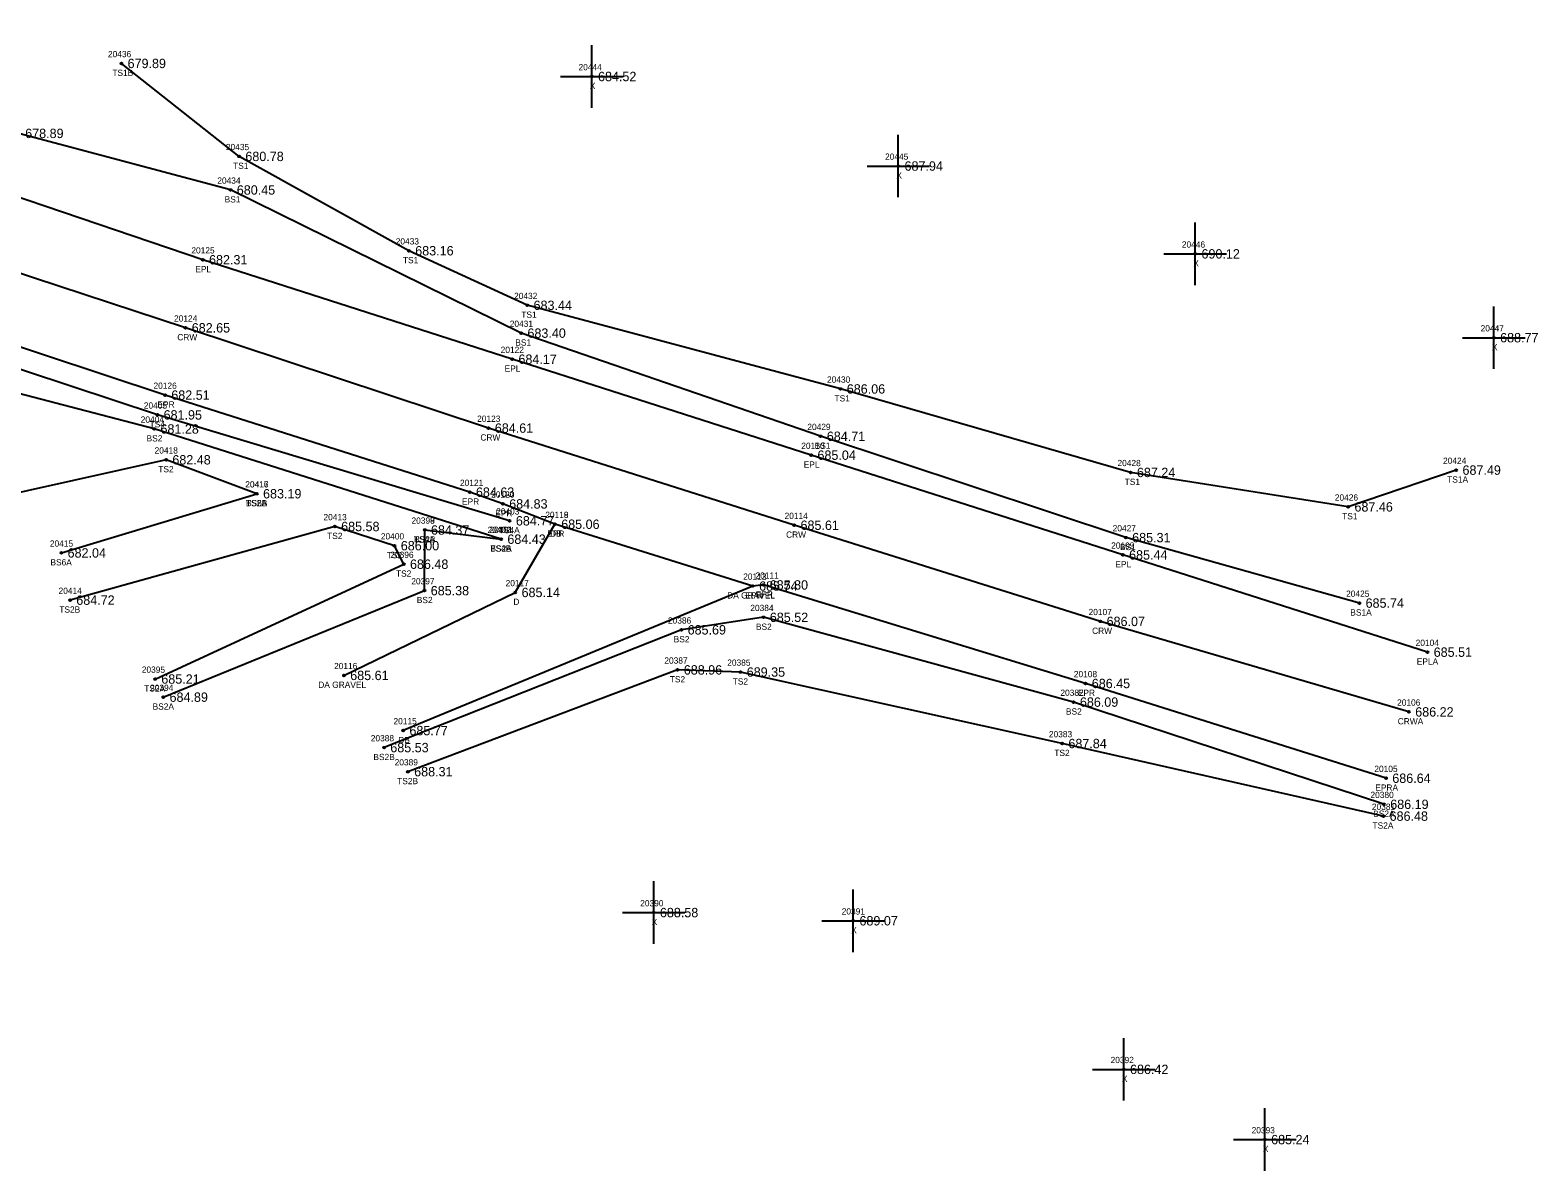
# Model space of a CAD drawing. Extents: x 1655675 to 1657082, y 1004080 to 1005193.
# Drawn here: x 1656840.9 to 1657082.1, y 1004326.1 to 1004508.6 of the extents above; entities that cross this region are included whole.
import ezdxf

# ---------------------------------------------------------------- set-up
doc = ezdxf.new("R2010")
doc.units = 0
for name, color, linetype in [('RD_DTM_BkLn1', 7, 'Continuous'), ('RD_DTM_BkLn2', 7, 'Continuous'), ('RD_DTM_BkLn_txCode', 7, 'Continuous'), ('RD_EX_Driveway', 7, 'Continuous'), ('RD_EX_Driveway_txCode', 7, 'Continuous'), ('RD_EX_Misc', 7, 'Continuous'), ('RD_EX_Misc_txCode', 7, 'Continuous'), ('RD_EX_Road', 7, 'Continuous'), ('RD_EX_Road_txCode', 7, 'Continuous'), ('RD_EX_TX_Driveway_ELEV', 7, 'Continuous'), ('RD_EX_TX_Misc_ELEV', 7, 'Continuous'), ('RD_EX_TX_Road_ELEV', 7, 'Continuous'), ('RD_HC_Survey_ELEV', 7, 'Continuous'), ('RD_HC_Survey_txCode', 7, 'Continuous'), ('RD_SMD_Locator', 7, 'Continuous')]:
    doc.layers.add(name, color=color, linetype=linetype)

msp = doc.modelspace()

# ---------------------------------------------------------------- linework, layer by layer
at = {"layer": 'RD_DTM_BkLn1'}
msp.add_lwpolyline([(1657061.44, 1004399.53), (1657012.07, 1004414.01), (1656963.11, 1004429.39), (1656914.21, 1004444.93), (1656865.73, 1004460.97), (1656817.07, 1004476.94), (1656768.62, 1004493.15), (1656720.24, 1004509.39), (1656671.72, 1004525.86), (1656623.45, 1004542.51), (1656574.61, 1004558.72), (1656526.43, 1004574.41), (1656478.09, 1004590.75), (1656429.6, 1004607.09), (1656401.58, 1004616.48)], dxfattribs=at)
at = {"layer": 'RD_DTM_BkLn2'}
for p, q in [((1656845.87, 1004424.96), (1656877.14, 1004434.43)), ((1656904, 1004428.63), (1656916.22, 1004427.16))]:
    msp.add_line(p, q, dxfattribs=at)
for points in [[(1656916.22, 1004427.16), (1656860.73, 1004444.79), (1656812.26, 1004457.45), (1656804.38, 1004456.52), (1656762.93, 1004472.17), (1656714, 1004488.45), (1656666.66, 1004507.38), (1656620.12, 1004527.68), (1656568.41, 1004543.92), (1656526.96, 1004552.22)], [(1656917.58, 1004430.1), (1656861.23, 1004447.04), (1656812.34, 1004463.2), (1656764.22, 1004476.47), (1656716.73, 1004495.56), (1656667.72, 1004513.97), (1656620.99, 1004529.43), (1656569.32, 1004546.11), (1656560.19, 1004551.77)], [(1656877.14, 1004434.43), (1656862.63, 1004439.86), (1656832.96, 1004433.22), (1656804.97, 1004442.37), (1656761.39, 1004459.38), (1656711.4, 1004477.11), (1656669.22, 1004500.61), (1656617.04, 1004520), (1656542.14, 1004544.84), (1656525.4, 1004509.94)], [(1657069, 1004438.21), (1657051.72, 1004432.33), (1657016.92, 1004437.84), (1656970.51, 1004451.19), (1656920.41, 1004464.57), (1656901.48, 1004473.3), (1656874.31, 1004488.39), (1656855.47, 1004503.26)], [(1657053.5, 1004416.94), (1657016.16, 1004427.41), (1656967.32, 1004443.62), (1656919.43, 1004460.12), (1656872.94, 1004483.02), (1656839.09, 1004492.07), (1656828.41, 1004493.57)], [(1656860.86, 1004404.79), (1656900.64, 1004423.16), (1656899.17, 1004426.12), (1656889.63, 1004429.19), (1656847.26, 1004417.41)], [(1656862.18, 1004401.89), (1656903.96, 1004418.93), (1656904, 1004428.63)], [(1657057.44, 1004384.75), (1657007.8, 1004401.1), (1656958.2, 1004414.66), (1656945.05, 1004412.66), (1656897.49, 1004393.82)], [(1657057.34, 1004382.86), (1657005.96, 1004394.47), (1656954.51, 1004405.91), (1656944.44, 1004406.25), (1656901.31, 1004389.97)]]:
    msp.add_lwpolyline(points, dxfattribs=at)
at = {"layer": 'RD_EX_Driveway'}
msp.add_line((1656956.49, 1004419.67), (1656900.55, 1004396.54), dxfattribs=at)
msp.add_lwpolyline([(1656891.08, 1004405.37), (1656918.49, 1004418.64), (1656924.83, 1004429.55)], dxfattribs=at)
at = {"layer": 'RD_EX_Misc'}
for p, q in [((1656930.72, 1004496.17), (1656930.72, 1004506.17)), ((1656925.72, 1004501.17), (1656935.72, 1004501.17)), ((1656979.75, 1004481.85), (1656979.75, 1004491.85)), ((1656974.75, 1004486.85), (1656984.75, 1004486.85)), ((1657027.25, 1004467.8), (1657027.25, 1004477.8)), ((1657022.25, 1004472.8), (1657032.25, 1004472.8)), ((1657075.02, 1004454.39), (1657075.02, 1004464.39)), ((1657070.02, 1004459.39), (1657080.02, 1004459.39)), ((1656940.62, 1004362.43), (1656940.62, 1004372.43)), ((1656972.54, 1004361.12), (1656972.54, 1004371.12)), ((1656935.62, 1004367.43), (1656945.62, 1004367.43)), ((1656967.54, 1004366.12), (1656977.54, 1004366.12)), ((1657015.82, 1004337.35), (1657015.82, 1004347.35)), ((1657010.82, 1004342.35), (1657020.82, 1004342.35)), ((1657038.39, 1004326.12), (1657038.39, 1004336.12)), ((1657033.39, 1004331.12), (1657043.39, 1004331.12))]:
    msp.add_line(p, q, dxfattribs=at)
at = {"layer": 'RD_EX_Road'}
for points in [[(1657064.39, 1004409.09), (1657015.67, 1004424.64), (1656965.82, 1004440.6), (1656917.99, 1004455.95), (1656868.5, 1004471.86), (1656826.53, 1004486.06), (1656801.74, 1004494.51), (1656772.14, 1004504.27), (1656723.45, 1004520.92), (1656674.94, 1004537.34), (1656626.5, 1004553.88), (1656578.27, 1004569.52), (1656529.18, 1004584.75), (1656481.5, 1004600.51), (1656432.67, 1004617.14), (1656404.34, 1004625.82)], [(1657057.77, 1004388.92), (1657009.7, 1004404.08), (1656958.18, 1004419.84), (1656956.49, 1004419.67), (1656924.83, 1004429.55), (1656916.51, 1004432.8), (1656911.19, 1004434.68), (1656862.46, 1004450.21), (1656813.53, 1004466.42), (1656765.51, 1004482.33), (1656716.81, 1004499.14), (1656668.6, 1004515.93), (1656620.24, 1004532.54), (1656571.72, 1004548.37), (1656523.3, 1004563.77), (1656474.37, 1004580.29), (1656426.43, 1004596.82), (1656398.22, 1004606.78)]]:
    msp.add_lwpolyline(points, dxfattribs=at)
at = {"layer": 'RD_SMD_Locator'}
for centre in [(1656855.47, 1004503.26), (1656930.72, 1004501.17), (1656874.31, 1004488.39), (1656979.75, 1004486.85), (1656872.94, 1004483.02), (1656868.5, 1004471.86), (1656901.48, 1004473.3), (1657027.25, 1004472.8), (1656920.41, 1004464.57), (1656865.73, 1004460.97), (1656919.43, 1004460.12), (1657075.02, 1004459.39), (1656917.99, 1004455.95), (1656862.46, 1004450.21), (1656970.51, 1004451.19), (1656861.23, 1004447.04), (1656860.73, 1004444.79), (1656914.21, 1004444.93), (1656967.32, 1004443.62), (1656862.63, 1004439.86), (1656965.82, 1004440.6), (1657016.92, 1004437.84), (1657069, 1004438.21), (1656877.14, 1004434.43), (1656877.14, 1004434.43), (1656911.19, 1004434.68), (1656916.51, 1004432.8), (1656917.58, 1004430.1), (1657051.72, 1004432.33), (1656889.63, 1004429.19), (1656904, 1004428.63), (1656904, 1004428.63), (1656924.83, 1004429.55), (1656924.83, 1004429.55), (1656963.11, 1004429.39), (1656899.17, 1004426.12), (1656916.22, 1004427.16), (1656916.22, 1004427.16), (1657016.16, 1004427.41), (1656845.87, 1004424.96), (1656900.64, 1004423.16), (1657015.67, 1004424.64), (1656903.96, 1004418.93), (1656918.49, 1004418.64), (1656956.49, 1004419.67), (1656956.49, 1004419.67), (1656958.18, 1004419.84), (1656847.26, 1004417.41), (1657053.5, 1004416.94), (1656958.2, 1004414.66), (1657012.07, 1004414.01), (1656945.05, 1004412.66), (1657064.39, 1004409.09), (1656944.44, 1004406.25), (1656954.51, 1004405.91), (1656860.86, 1004404.79), (1656891.08, 1004405.37), (1657009.7, 1004404.08), (1656862.18, 1004401.89), (1657007.8, 1004401.1), (1657061.44, 1004399.53), (1656900.55, 1004396.54), (1656897.49, 1004393.82), (1657005.96, 1004394.47), (1656901.31, 1004389.97), (1657057.77, 1004388.92), (1657057.44, 1004384.75), (1657057.34, 1004382.86), (1656940.62, 1004367.43), (1656972.54, 1004366.12), (1657015.82, 1004342.35), (1657038.39, 1004331.12)]:
    msp.add_circle(centre, 0.15, dxfattribs=at)

# ---------------------------------------------------------------- texts
at = {"layer": 'RD_DTM_BkLn_txCode'}
for s, p in [('20436', (1656853.33, 1004504.26)), ('TS1B', (1656854.03, 1004501.26)), ('20435', (1656872.19, 1004489.39)), ('TS1', (1656873.35, 1004486.39)), ('20434', (1656870.82, 1004484.02)), ('BS1', (1656871.99, 1004481.02)), ('20433', (1656899.36, 1004474.3)), ('TS1', (1656900.51, 1004471.3)), ('20432', (1656918.29, 1004465.57)), ('20431', (1656917.6, 1004461.12)), ('TS1', (1656919.45, 1004462.57)), ('BS1', (1656918.49, 1004458.12)), ('20430', (1656968.35, 1004452.19)), ('TS1', (1656969.55, 1004449.19)), ('20405', (1656859.07, 1004448.04)), ('20404', (1656858.57, 1004445.79)), ('TS4', (1656859.99, 1004445.04)), ('20429', (1656965.2, 1004444.62)), ('BS2', (1656859.5, 1004442.79)), ('BS1', (1656966.37, 1004441.62)), ('20418', (1656860.79, 1004440.86)), ('20428', (1657014.81, 1004438.84)), ('20424', (1657066.89, 1004439.21)), ('TS2', (1656861.38, 1004437.86)), ('20416', (1656875.28, 1004435.43)), ('20417', (1656875.3, 1004435.43)), ('TS1', (1657015.96, 1004435.84)), ('TS1A', (1657067.55, 1004436.21)), ('TS2A', (1656875.4, 1004432.43)), ('BS6B', (1656875.41, 1004432.43)), ('20426', (1657049.58, 1004433.33)), ('20413', (1656887.8, 1004430.19)), ('20398', (1656901.88, 1004429.63)), ('20399', (1656901.88, 1004429.63)), ('20403', (1656915.42, 1004431.1)), ('TS1', (1657050.76, 1004430.33)), ('TS2', (1656888.39, 1004427.19)), ('20400', (1656896.98, 1004427.12)), ('20402', (1656914.06, 1004428.16)), ('20401', (1656914.35, 1004428.16)), ('TS4A', (1656915.85, 1004428.1)), ('20427', (1657014.04, 1004428.41)), ('20415', (1656844.04, 1004425.96)), ('TS4A', (1656902.27, 1004426.63)), ('BS2B', (1656902.3, 1004426.63)), ('TS4B', (1656914.51, 1004425.16)), ('BS2A', (1656914.51, 1004425.16)), ('BS1', (1657015.22, 1004425.41)), ('BS6A', (1656844.13, 1004422.96)), ('TS2', (1656897.93, 1004424.12)), ('20396', (1656898.5, 1004424.16)), ('TS2', (1656899.4, 1004421.16)), ('20397', (1656901.85, 1004419.93)), ('20414', (1656845.43, 1004418.41)), ('20425', (1657051.38, 1004417.94)), ('TS2B', (1656845.55, 1004415.41)), ('BS2', (1656902.73, 1004416.93)), ('20384', (1656956.08, 1004415.66)), ('BS1A', (1657052.06, 1004414.94)), ('20386', (1656942.91, 1004413.66)), ('BS2', (1656956.97, 1004412.66)), ('BS2', (1656943.82, 1004410.66)), ('20395', (1656858.74, 1004405.79)), ('20387', (1656942.33, 1004407.25)), ('20385', (1656952.39, 1004406.91)), ('TS2A', (1656859.13, 1004402.79)), ('20394', (1656860.07, 1004402.89)), ('TS2', (1656943.2, 1004404.25)), ('TS2', (1656953.26, 1004403.91)), ('20382', (1657005.68, 1004402.1)), ('BS2A', (1656860.47, 1004399.89)), ('BS2', (1657006.57, 1004399.1)), ('20383', (1657003.84, 1004395.47)), ('20388', (1656895.37, 1004394.82)), ('BS2B', (1656895.79, 1004391.82)), ('20389', (1656899.19, 1004390.97)), ('TS2', (1657004.71, 1004392.47)), ('TS2B', (1656899.59, 1004387.97)), ('20380', (1657055.28, 1004385.75)), ('20381', (1657055.51, 1004383.86)), ('TS2A', (1657055.61, 1004380.86)), ('BS2A', (1657055.72, 1004382.75))]:
    msp.add_text(s, height=1, dxfattribs=at).set_placement(p)
at = {"layer": 'RD_EX_Driveway_txCode'}
for s, p in [('20119', (1656923.28, 1004430.55)), ('DB', (1656924.05, 1004427.55)), ('20117', (1656916.94, 1004419.64)), ('20112', (1656954.94, 1004420.67)), ('DA GRAVEL', (1656952.38, 1004417.67)), ('D', (1656918.18, 1004416.64)), ('20116', (1656889.5, 1004406.37)), ('DA GRAVEL', (1656886.97, 1004403.37)), ('20115', (1656899, 1004397.54)), ('DB', (1656899.77, 1004394.54))]:
    msp.add_text(s, height=1, dxfattribs=at).set_placement(p)
at = {"layer": 'RD_EX_Misc_txCode'}
for s, p in [('20444', (1656928.6, 1004502.17)), ('X', (1656930.4, 1004499.17)), ('20445', (1656977.63, 1004487.85)), ('X', (1656979.44, 1004484.85)), ('20446', (1657025.11, 1004473.8)), ('X', (1657026.94, 1004470.8)), ('20447', (1657072.9, 1004460.39)), ('X', (1657074.7, 1004457.39)), ('20390', (1656938.47, 1004368.43)), ('20391', (1656970.7, 1004367.12)), ('X', (1656940.31, 1004365.43)), ('X', (1656972.22, 1004364.12)), ('20392', (1657013.71, 1004343.35)), ('X', (1657015.51, 1004340.35)), ('20393', (1657036.27, 1004332.12)), ('X', (1657038.07, 1004329.12))]:
    msp.add_text(s, height=1, dxfattribs=at).set_placement(p)
at = {"layer": 'RD_EX_Road_txCode'}
for s, p in [('20125', (1656866.67, 1004472.86)), ('EPL', (1656867.3, 1004469.86)), ('20122', (1656916.15, 1004456.95)), ('EPL', (1656916.78, 1004453.95)), ('20126', (1656860.61, 1004451.21)), ('EPR', (1656861.24, 1004448.21)), ('20110', (1656964.23, 1004441.6)), ('EPL', (1656964.62, 1004438.6)), ('20121', (1656909.64, 1004435.68)), ('EPR', (1656909.96, 1004432.68)), ('20120', (1656914.63, 1004433.8)), ('EPR', (1656915.28, 1004430.8)), ('20118', (1656923.28, 1004430.55)), ('EPR', (1656923.6, 1004427.55)), ('20109', (1657013.8, 1004425.64)), ('EPL', (1657014.47, 1004422.64)), ('20113', (1656954.94, 1004420.67)), ('20111', (1656956.91, 1004420.84)), ('EPR', (1656955.26, 1004417.67)), ('EPR', (1656956.95, 1004417.84)), ('20104', (1657062.51, 1004410.09)), ('20108', (1657007.83, 1004405.08)), ('EPLA', (1657062.69, 1004407.09)), ('EPR', (1657008.47, 1004402.08)), ('20105', (1657055.9, 1004389.92)), ('EPRA', (1657056.05, 1004386.92))]:
    msp.add_text(s, height=1, dxfattribs=at).set_placement(p)
at = {"layer": 'RD_EX_TX_Driveway_ELEV'}
for s, p in [('685.06', (1656925.83, 1004428.8)), ('685.14', (1656919.49, 1004417.89)), ('685.74', (1656957.49, 1004418.92)), ('685.61', (1656892.08, 1004404.62)), ('685.77', (1656901.55, 1004395.79))]:
    msp.add_text(s, height=1.5, dxfattribs=at).set_placement(p)
at = {"layer": 'RD_EX_TX_Misc_ELEV'}
for s, p in [('679.89', (1656856.47, 1004502.51)), ('684.52', (1656931.72, 1004500.42)), ('678.89', (1656840.09, 1004491.32)), ('680.78', (1656875.31, 1004487.64)), ('687.94', (1656980.75, 1004486.1)), ('680.45', (1656873.94, 1004482.27)), ('683.16', (1656902.48, 1004472.55)), ('690.12', (1657028.25, 1004472.05)), ('683.44', (1656921.41, 1004463.82)), ('683.40', (1656920.43, 1004459.37)), ('688.77', (1657076.02, 1004458.64)), ('686.06', (1656971.51, 1004450.44)), ('681.95', (1656862.23, 1004446.29)), ('681.28', (1656861.73, 1004444.04)), ('684.71', (1656968.32, 1004442.87)), ('682.48', (1656863.63, 1004439.11)), ('687.24', (1657017.92, 1004437.09)), ('687.49', (1657070, 1004437.46)), ('683.19', (1656878.14, 1004433.68)), ('683.19', (1656878.14, 1004433.68)), ('687.46', (1657052.72, 1004431.58)), ('684.77', (1656918.58, 1004429.35)), ('685.58', (1656890.63, 1004428.44)), ('684.37', (1656905, 1004427.88)), ('684.37', (1656905, 1004427.88)), ('684.43', (1656917.22, 1004426.41)), ('684.43', (1656917.22, 1004426.41)), ('685.31', (1657017.16, 1004426.66)), ('682.04', (1656846.87, 1004424.21)), ('686.00', (1656900.17, 1004425.37)), ('686.48', (1656901.64, 1004422.41)), ('684.72', (1656848.26, 1004416.66)), ('685.38', (1656904.96, 1004418.18)), ('685.74', (1657054.5, 1004416.19)), ('685.69', (1656946.05, 1004411.91)), ('685.52', (1656959.2, 1004413.91)), ('688.96', (1656945.44, 1004405.5)), ('689.35', (1656955.51, 1004405.16)), ('685.21', (1656861.86, 1004404.04)), ('684.89', (1656863.18, 1004401.14)), ('686.09', (1657008.8, 1004400.35)), ('685.53', (1656898.49, 1004393.07)), ('687.84', (1657006.96, 1004393.72)), ('688.31', (1656902.31, 1004389.22)), ('686.19', (1657058.44, 1004384)), ('686.48', (1657058.34, 1004382.11)), ('688.58', (1656941.62, 1004366.68)), ('689.07', (1656973.54, 1004365.37)), ('686.42', (1657016.82, 1004341.6)), ('685.24', (1657039.39, 1004330.37))]:
    msp.add_text(s, height=1.5, dxfattribs=at).set_placement(p)
at = {"layer": 'RD_EX_TX_Road_ELEV'}
for s, p in [('682.31', (1656869.5, 1004471.11)), ('684.17', (1656918.99, 1004455.2)), ('682.51', (1656863.46, 1004449.46)), ('685.04', (1656966.82, 1004439.85)), ('684.63', (1656912.19, 1004433.93)), ('684.83', (1656917.51, 1004432.05)), ('685.06', (1656925.83, 1004428.8)), ('685.44', (1657016.67, 1004423.89)), ('685.80', (1656959.18, 1004419.09)), ('685.74', (1656957.49, 1004418.92)), ('685.51', (1657065.39, 1004408.34)), ('686.45', (1657010.7, 1004403.33)), ('686.64', (1657058.77, 1004388.17))]:
    msp.add_text(s, height=1.5, dxfattribs=at).set_placement(p)
at = {"layer": 'RD_HC_Survey_ELEV'}
for s, p in [('682.65', (1656866.73, 1004460.22)), ('684.61', (1656915.21, 1004444.18)), ('685.61', (1656964.11, 1004428.64)), ('686.07', (1657013.07, 1004413.26)), ('686.22', (1657062.44, 1004398.78))]:
    msp.add_text(s, height=1.5, dxfattribs=at).set_placement(p)
at = {"layer": 'RD_HC_Survey_txCode'}
for s, p in [('20124', (1656863.9, 1004461.97)), ('CRW', (1656864.42, 1004458.97)), ('20123', (1656912.38, 1004445.93)), ('CRW', (1656912.9, 1004442.93)), ('20114', (1656961.56, 1004430.39)), ('CRW', (1656961.8, 1004427.39)), ('20107', (1657010.19, 1004415.01)), ('CRW', (1657010.75, 1004412.01)), ('20106', (1657059.54, 1004400.53)), ('CRWA', (1657059.64, 1004397.53))]:
    msp.add_text(s, height=1, dxfattribs=at).set_placement(p)

doc.saveas('drawing.dxf')
